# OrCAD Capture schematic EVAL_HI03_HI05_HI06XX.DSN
size A; title: EVAL HI03_HI05_HI06XX; rev: A1; note: 1
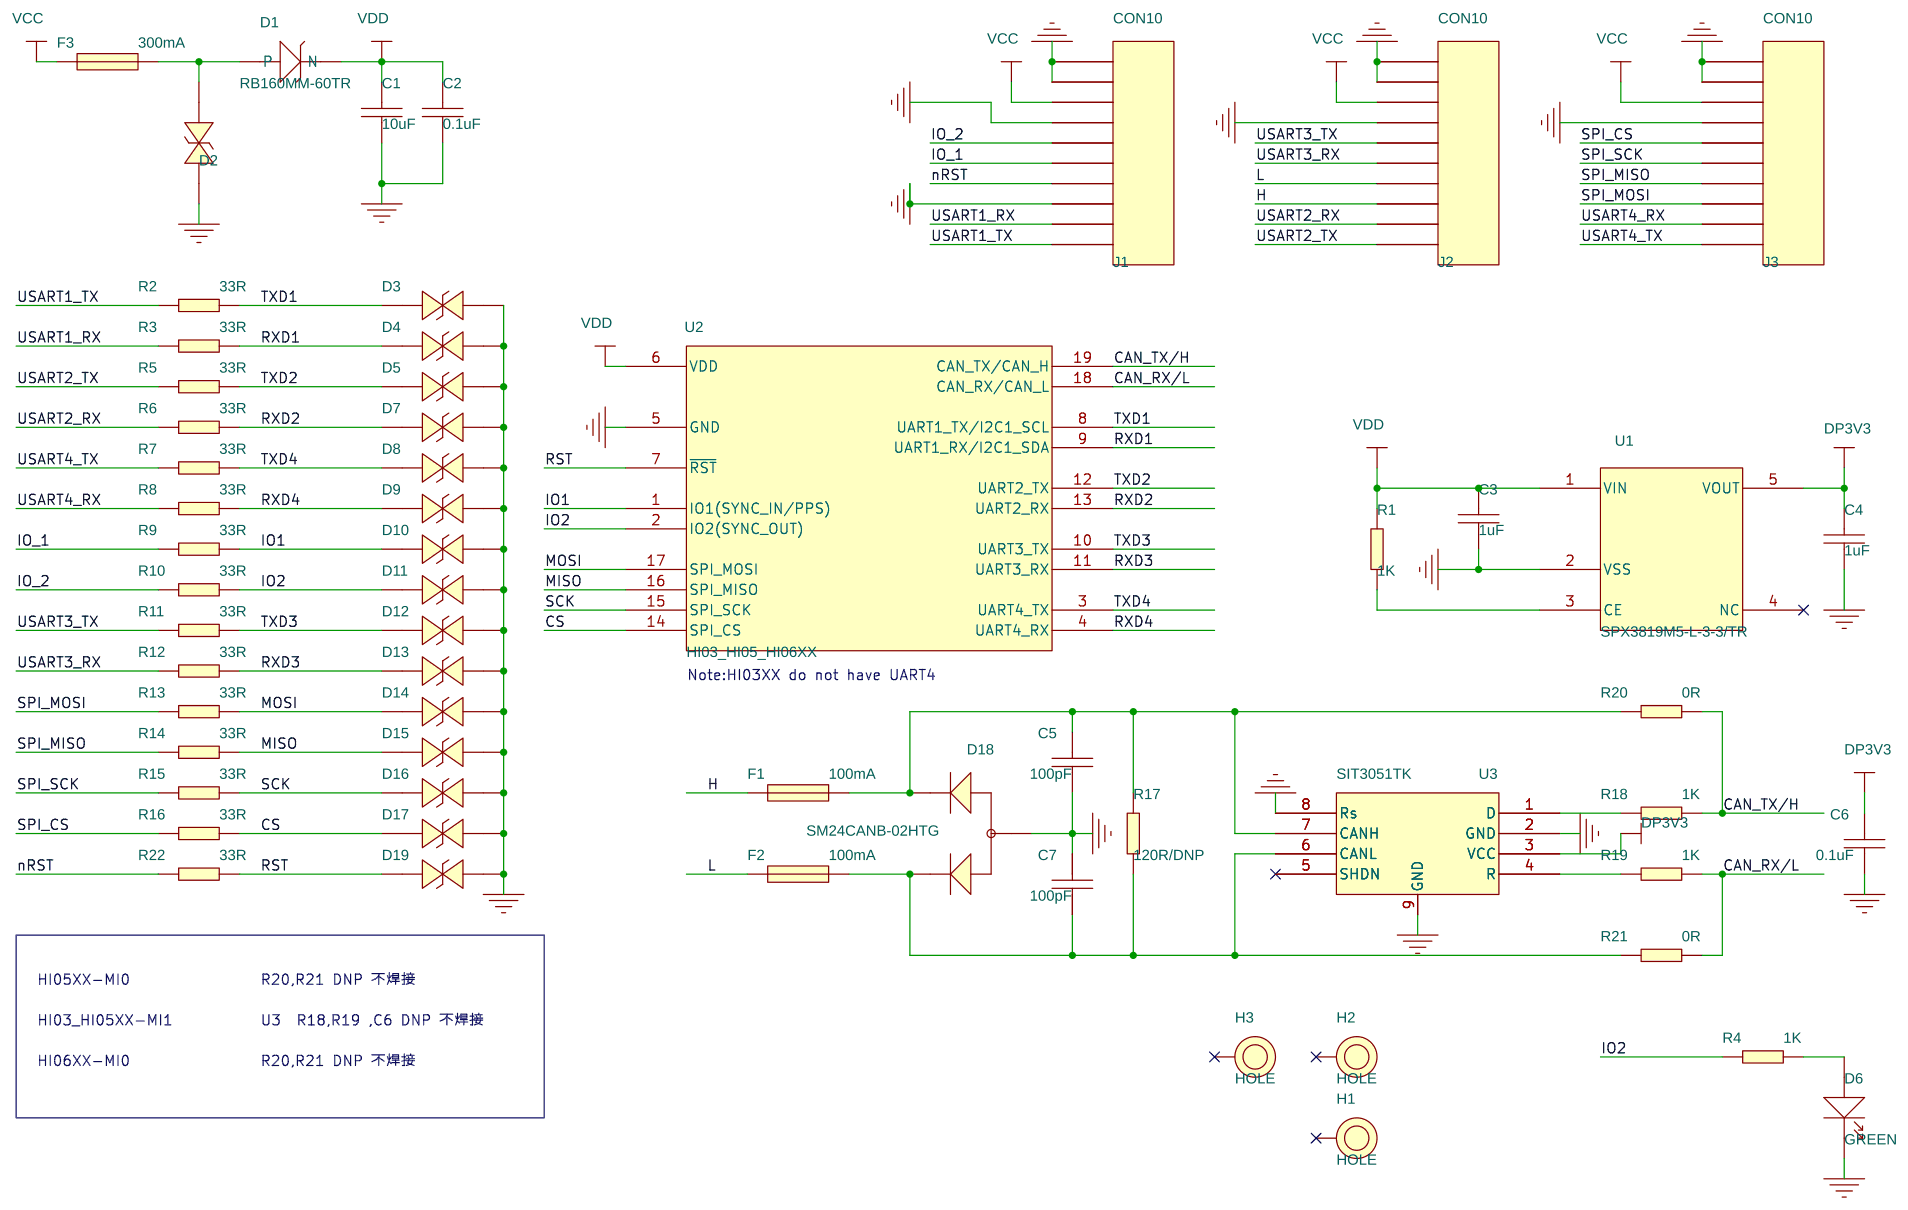
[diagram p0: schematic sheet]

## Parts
C1  10uF  [C0603]
C2  0.1uF  [C0402]
C3  1uF  [C0402]
C4  1uF  [C0402]
C5  100pF  [C0402]
C6  0.1uF  [C0402]
C7  100pF  [C0402]
D1  RB160MM-60TR  [SOD123FL]
D2  SDD32A05L01  [DO-214AC]
D3  SBD52C05L01  [SOD-523]
D4  SBD52C05L01  [SOD-523]
D5  SBD52C05L01  [SOD-523]
D6  GREEN  [LED0402]
D7  SBD52C05L01  [SOD-523]
D8  SBD52C05L01  [SOD-523]
D9  SBD52C05L01  [SOD-523]
D10  SBD52C05L01  [SOD-523]
D11  SBD52C05L01  [SOD-523]
D12  SBD52C05L01  [SOD-523]
D13  SBD52C05L01  [SOD-523]
D14  SBD52C05L01  [SOD-523]
D15  SBD52C05L01  [SOD-523]
D16  SBD52C05L01  [SOD-523]
D17  SBD52C05L01  [SOD-523]
D18  SM24CANB-02HTG  [SOT23-3-0_95]
D19  SBD52C05L01  [SOD-523]
F1  100mA  [F0603]
F2  100mA  [F0603]
F3  300mA  [F0603]
H1  HOLE  [HOLE-2-MM]
H2  HOLE  [HOLE-2-MM]
H3  HOLE  [HOLE-2-MM]
J1  CON10  [5015680807_1]
J2  CON10  [5015680807_1]
J3  CON10  [5015680807_1]
R1  1K  [R0402]
R2  33R  [R0402]
R3  33R  [R0402]
R4  1K  [R0402]
R5  33R  [R0402]
R6  33R  [R0402]
R7  33R  [R0402]
R8  33R  [R0402]
R9  33R  [R0402]
R10  33R  [R0402]
R11  33R  [R0402]
R12  33R  [R0402]
R13  33R  [R0402]
R14  33R  [R0402]
R15  33R  [R0402]
R16  33R  [R0402]
R17  120R/DNP  [R0805]
R18  1K  [R0402]
R19  1K  [R0402]
R20  0R  [R0402]
R21  0R  [R0402]
R22  33R  [R0402]
U1  SPX3819M5-L-3-3/TR  [SOT23-5-0_95]
U2  HI03_HI05_HI06XX  [HI02_HI05_HI06]
U3  SIT3051TK  [HVSON8]

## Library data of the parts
C1-C7 = Capacity_Nonpolarity
D1 = diode
D2-D5 D7-D17 D19 = DIODE_BI-DIR_TRIG
D6 = LED
D18 = BAT54A_SOT
F1-F3 = Fuse
H1-H3 = HOLE
J1-J3 = CON10
R1-R22 = Res
U1 = XC6210
U2 = HI05_HI06XX
U3 = SIT3051TK

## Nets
GND: C1.1 C2.1 C3.2 C4.1 C5.2 C6.2 C7.1 D2.1 D3.1 D4.1 D5.1 D6.2(-) D7.1 D8.1 D9.1 D10.1 D11.1 D12.1 D13.1 D14.1 D15.1 D16.1 D17.1 D18.3 D19.1 J1.3 J1.7 J1.9 J1.10 J2.7 J2.9 J2.10 J3.7 J3.9 J3.10 U1.2(VSS) U2.5(GND) U3.2(GND) U3.8(Rs) U3.9(GND)
VCC: F3.1 J1.8 J2.8 J3.8
VDD: C1.2 C2.2 C3.1 D1.2(N) R1.2 U1.1(VIN) U2.6(VDD)
CAN_RX/L: R19.1 R21.1 U2.18(CAN_RX/CAN_L)
CAN_TX/H: R18.1 R20.1 U2.19(CAN_TX/CAN_H)
CS: D17.2 R16.1 U2.14(SPI_CS)
DP3V3: C4.2 C6.1 U1.5(VOUT) U3.3(VCC)
H: F1.1 J2.3
IO1: D10.2 R9.1 U2.1(IO1(SYNC_IN/PPS))
IO2: D11.2 R4.1 R10.1 U2.2(IO2(SYNC_OUT))
IO_1: J1.5 R9.2
IO_2: J1.6 R10.2
L: F2.1 J2.4
MISO: D15.2 R14.1 U2.16(SPI_MISO)
MOSI: D14.2 R13.1 U2.17(SPI_MOSI)
nRST: J1.4 R22.2
RST: D19.2 R22.1 U2.7(~{RST})
RXD1: D4.2 R3.1 U2.9(UART1_RX/I2C1_SDA)
RXD2: D7.2 R6.1 U2.13(UART2_RX)
RXD3: D13.2 R12.1 U2.11(UART3_RX)
RXD4: D9.2 R8.1 U2.4(UART4_RX)
SCK: D16.2 R15.1 U2.15(SPI_SCK)
SPI_CS: J3.6 R16.2
SPI_MISO: J3.4 R14.2
SPI_MOSI: J3.3 R13.2
SPI_SCK: J3.5 R15.2
TXD1: D3.2 R2.1 U2.8(UART1_TX/I2C1_SCL)
TXD2: D5.2 R5.1 U2.12(UART2_TX)
TXD3: D12.2 R11.1 U2.10(UART3_TX)
TXD4: D8.2 R7.1 U2.3(UART4_TX)
USART1_RX: J1.2 R3.2
USART1_TX: J1.1 R2.2
USART2_RX: J2.2 R6.2
USART2_TX: J2.1 R5.2
USART3_RX: J2.5 R12.2
USART3_TX: J2.6 R11.2
USART4_RX: J3.2 R8.2
USART4_TX: J3.1 R7.2
N2198535: D6.1(+) R4.2
N2224750: R1.1 U1.3(CE)
N2242059: C5.1 D18.1 F1.2 R17.2 R20.2 U3.7(CANH)
N2242241: R18.2 U3.1(D)
N2242331: C7.2 D18.2 F2.2 R17.1 R21.2 U3.6(CANL)
N2242381: R19.2 U3.4(R)
N2269635: D1.1(P) D2.2 F3.2

Not connected (* = marked no-connect by the designer): H1 1*; H2 1*; H3 1*; U1 4(NC)*; U3 5(SHDN)*

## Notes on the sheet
- Note:HI03XX do not have UART4
- HI05XX-MI0
- R20,R21 DNP 不焊接
- HI03_HI05XX-MI1
- U3  R18,R19 ,C6 DNP 不焊接
- HI06XX-MI0
- R20,R21 DNP 不焊接
